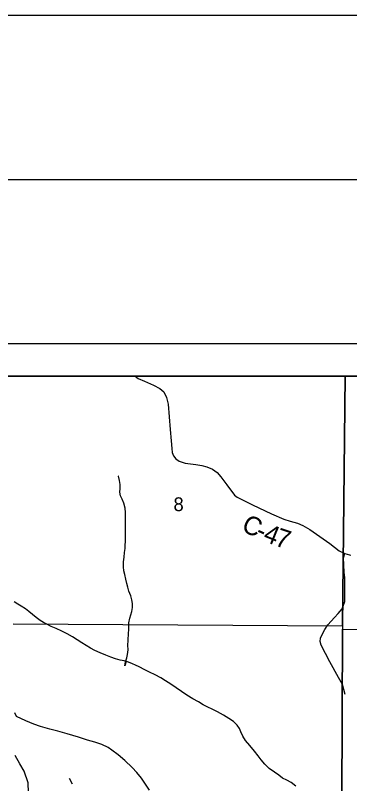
# Model space of a CAD drawing. Extents: x 0 to 34, y 0 to 22.
# Drawn here: x 4.552 to 5.572, y 19.658 to 22 of the extents above; entities that cross this region are included whole.
import ezdxf

# ---------------------------------------------------------------- set-up
doc = ezdxf.new("R2010")
doc.units = 0
for name, color, linetype in [('Default', 7, 'Continuous'), ('GM_X_County_Road', 7, 'Continuous'), ('GM_X_County_Road_Text', 7, 'Continuous'), ('GM_X_Minor_River', 7, 'Continuous'), ('GM_X_Section', 7, 'Continuous'), ('GM_X_Section_Text', 7, 'Continuous'), ('GM_X_State_Route', 7, 'Continuous'), ('GM_X_Township_Road', 7, 'Continuous'), ('SH_Border', 7, 'Continuous'), ('SH_Cut_Line', 7, 'Continuous'), ('SH_Data', 7, 'Continuous')]:
    doc.layers.add(name, color=color, linetype=linetype)

msp = doc.modelspace()

# ---------------------------------------------------------------- linework, layer by layer
at = {"layer": 'Default'}
for p, q in [((7.8225, 20.9), (2.1, 20.9)), ((5.558, 20.9), (4.5485, 20.9)), ((5.5506, 20.1397), (5.558, 20.9)), ((5.558, 20.9), (5.5506, 20.1397)), ((6.4715, 20.9), (5.558, 20.9)), ((4.5449, 20.1449), (5.5506, 20.1397)), ((5.5506, 20.1397), (5.5505, 20.1287)), ((5.5505, 20.1287), (6.4665, 20.1167))]:
    msp.add_line(p, q, dxfattribs=at)
at = {"layer": 'GM_X_County_Road'}
for p, q in [((4.9181, 20.9), (4.9265, 20.8933)), ((4.9265, 20.8933), (4.9456, 20.8848)), ((4.9456, 20.8848), (4.9739, 20.8727)), ((4.9739, 20.8727), (4.9933, 20.8625)), ((4.9933, 20.8625), (5.0055, 20.8526)), ((5.0055, 20.8526), (5.0136, 20.835)), ((5.0136, 20.835), (5.0181, 20.8148)), ((5.0181, 20.8148), (5.0248, 20.7375)), ((5.0248, 20.7375), (5.0275, 20.7027)), ((5.0275, 20.7027), (5.0295, 20.6794)), ((5.0295, 20.6794), (5.0307, 20.6679)), ((5.0307, 20.6679), (5.0341, 20.6576)), ((5.0341, 20.6576), (5.042, 20.6481)), ((5.042, 20.6481), (5.0523, 20.641)), ((5.0523, 20.641), (5.0703, 20.6354)), ((5.0703, 20.6354), (5.1027, 20.6307)), ((5.1027, 20.6307), (5.1207, 20.6279)), ((5.1207, 20.6279), (5.1359, 20.6241)), ((5.1359, 20.6241), (5.1537, 20.6171)), ((5.1537, 20.6171), (5.1678, 20.6066)), ((5.1678, 20.6066), (5.1794, 20.5932)), ((5.1794, 20.5932), (5.1972, 20.5691)), ((5.1972, 20.5691), (5.2206, 20.5378)), ((5.2206, 20.5378), (5.2293, 20.5313)), ((5.2293, 20.5313), (5.2756, 20.5081)), ((5.2756, 20.5081), (5.3338, 20.4804)), ((5.3338, 20.4804), (5.3711, 20.4649)), ((5.3711, 20.4649), (5.3907, 20.4587)), ((5.3907, 20.4587), (5.4131, 20.4521)), ((5.4131, 20.4521), (5.4296, 20.4454)), ((5.4296, 20.4454), (5.4508, 20.4332)), ((5.4508, 20.4332), (5.5114, 20.3899)), ((5.5114, 20.3899), (5.5405, 20.3679)), ((5.5405, 20.3679), (5.5573, 20.3596)), ((5.5573, 20.3596), (5.5717, 20.3552)), ((5.5717, 20.3552), (5.5757, 20.3547))]:
    msp.add_line(p, q, dxfattribs=at)
at = {"layer": 'GM_X_Minor_River'}
for p, q in [((4.8665, 20.595), (4.866, 20.5957)), ((4.8695, 20.5825), (4.8665, 20.595)), ((4.8722, 20.5697), (4.8695, 20.5825)), ((4.8714, 20.5583), (4.8722, 20.5697)), ((4.8706, 20.5465), (4.8714, 20.5583)), ((4.8729, 20.5351), (4.8706, 20.5465)), ((4.8778, 20.525), (4.8729, 20.5351)), ((4.8831, 20.5134), (4.8778, 20.525)), ((4.8866, 20.4979), (4.8831, 20.5134)), ((4.8878, 20.485), (4.8866, 20.4979)), ((4.8878, 20.4732), (4.8878, 20.485)), ((4.8878, 20.4611), (4.8878, 20.4732)), ((4.8885, 20.4512), (4.8878, 20.4611)), ((4.8881, 20.4394), (4.8885, 20.4512)), ((4.8884, 20.428), (4.8881, 20.4394)), ((4.8882, 20.4116), (4.8884, 20.428)), ((4.8875, 20.3854), (4.8883, 20.3968)), ((4.8883, 20.3968), (4.8882, 20.4116)), ((4.8855, 20.3629), (4.887, 20.3751)), ((4.887, 20.3751), (4.8875, 20.3854)), ((4.8837, 20.3484), (4.8855, 20.3629)), ((4.8816, 20.3194), (4.8819, 20.3343)), ((4.8819, 20.3343), (4.8837, 20.3484)), ((4.8827, 20.3073), (4.8816, 20.3194)), ((4.8857, 20.296), (4.8827, 20.3073)), ((4.8892, 20.2816), (4.8857, 20.296)), ((4.8919, 20.2688), (4.8892, 20.2816)), ((4.8949, 20.2575), (4.8919, 20.2688)), ((4.8987, 20.2447), (4.8949, 20.2575)), ((4.9041, 20.2304), (4.8987, 20.2447)), ((4.5601, 20.2052), (4.5488, 20.2124)), ((4.9075, 20.2187), (4.9041, 20.2304)), ((4.9094, 20.2078), (4.9075, 20.2187)), ((4.5698, 20.199), (4.5601, 20.2052)), ((4.5826, 20.1907), (4.5698, 20.199)), ((4.5931, 20.1826), (4.5826, 20.1907)), ((4.9079, 20.1826), (4.9098, 20.1952)), ((4.9098, 20.1952), (4.9094, 20.2078)), ((4.604, 20.1742), (4.5931, 20.1826)), ((4.6157, 20.1647), (4.604, 20.1742)), ((4.6278, 20.156), (4.6157, 20.1647)), ((4.8987, 20.1485), (4.9017, 20.1626)), ((4.9017, 20.1626), (4.9079, 20.1826)), ((4.6375, 20.1498), (4.6278, 20.156)), ((4.6479, 20.144), (4.6375, 20.1498)), ((4.661, 20.1372), (4.6479, 20.144)), ((4.8983, 20.1382), (4.8987, 20.1485)), ((4.6765, 20.1309), (4.661, 20.1372)), ((4.6934, 20.123), (4.6765, 20.1309)), ((4.71, 20.1148), (4.6934, 20.123)), ((4.8958, 20.0948), (4.8974, 20.1169)), ((4.8974, 20.1169), (4.8982, 20.1272)), ((4.8982, 20.1272), (4.8983, 20.1382)), ((4.7263, 20.1054), (4.71, 20.1148)), ((4.741, 20.0968), (4.7263, 20.1054)), ((4.7546, 20.0877), (4.741, 20.0968)), ((4.8955, 20.0807), (4.8958, 20.0948)), ((4.7678, 20.079), (4.7546, 20.0877)), ((4.781, 20.071), (4.7678, 20.079)), ((4.7945, 20.0638), (4.781, 20.071)), ((4.8959, 20.0666), (4.8955, 20.0807)), ((4.8107, 20.0571), (4.7945, 20.0638)), ((4.8284, 20.0501), (4.8107, 20.0571)), ((4.8438, 20.0441), (4.8284, 20.0501)), ((4.8922, 20.0414), (4.8945, 20.0522)), ((4.8945, 20.0522), (4.8959, 20.0666)), ((4.858, 20.0388), (4.8438, 20.0441)), ((4.8715, 20.0351), (4.858, 20.0388)), ((4.8845, 20.0321), (4.8715, 20.0351)), ((4.8968, 20.0283), (4.8845, 20.0321)), ((4.8897, 20.0305), (4.8857, 20.0177)), ((4.8857, 20.0177), (4.8884, 20.0288)), ((4.8884, 20.0288), (4.8922, 20.0414)), ((4.9095, 20.0233), (4.8968, 20.0283)), ((4.9191, 20.0191), (4.9095, 20.0233)), ((4.9295, 20.0141), (4.9191, 20.0191)), ((4.9473, 20.0051), (4.9295, 20.0141)), ((4.9616, 19.998), (4.9473, 20.0051)), ((4.979, 19.9898), (4.9616, 19.998)), ((4.9956, 19.9804), (4.979, 19.9898)), ((5.0103, 19.9721), (4.9956, 19.9804)), ((5.0262, 19.9612), (5.0103, 19.9721)), ((5.0425, 19.9503), (5.0262, 19.9612)), ((5.0589, 19.9394), (5.0425, 19.9503)), ((5.0756, 19.9278), (5.0589, 19.9394)), ((5.0938, 19.917), (5.0756, 19.9278)), ((5.1104, 19.9072), (5.0938, 19.917)), ((5.1255, 19.8986), (5.1104, 19.9072)), ((5.139, 19.8918), (5.1255, 19.8986)), ((5.1529, 19.8854), (5.139, 19.8918)), ((5.1692, 19.8767), (5.1529, 19.8854)), ((5.1874, 19.8667), (5.1692, 19.8767)), ((5.2036, 19.8569), (5.1874, 19.8667)), ((5.2176, 19.8475), (5.2036, 19.8569)), ((5.229, 19.8364), (5.2176, 19.8475)), ((5.2358, 19.8264), (5.229, 19.8364)), ((5.2403, 19.8159), (5.2358, 19.8264)), ((5.246, 19.8027), (5.2403, 19.8159)), ((5.2544, 19.7901), (5.246, 19.8027)), ((5.2674, 19.7741), (5.2544, 19.7901)), ((5.2813, 19.7574), (5.2674, 19.7741)), ((5.2928, 19.7426), (5.2813, 19.7574)), ((5.3023, 19.7304), (5.2928, 19.7426)), ((5.3129, 19.7178), (5.3023, 19.7304)), ((5.3267, 19.7045), (5.3129, 19.7178)), ((5.3426, 19.6936), (5.3267, 19.7045)), ((4.7268, 19.657), (4.7171, 19.6739)), ((5.3558, 19.6837), (5.3426, 19.6936)), ((5.3675, 19.6754), (5.3558, 19.6837)), ((5.3803, 19.6685), (5.3675, 19.6754)), ((5.3934, 19.6617), (5.3803, 19.6685)), ((5.4082, 19.6508), (5.3934, 19.6617))]:
    msp.add_line(p, q, dxfattribs=at)
at = {"layer": 'GM_X_Section'}
for p, q in [((4.5449, 20.1449), (5.5506, 20.1397)), ((5.5506, 20.1397), (5.5505, 20.1287)), ((5.5505, 20.1287), (5.5458, 19.1336)), ((5.5458, 19.1336), (5.5505, 20.1287)), ((5.5505, 20.1287), (6.4665, 20.1167))]:
    msp.add_line(p, q, dxfattribs=at)
at = {"layer": 'GM_X_State_Route'}
for p, q in [((4.5554, 19.8631), (4.5505, 19.8741)), ((4.5837, 19.8496), (4.5554, 19.8631)), ((4.6085, 19.8394), (4.5837, 19.8496)), ((4.6284, 19.8326), (4.6085, 19.8394)), ((4.6574, 19.8248), (4.6284, 19.8326)), ((4.6821, 19.8184), (4.6574, 19.8248)), ((4.7103, 19.8103), (4.6821, 19.8184)), ((4.7447, 19.7999), (4.7103, 19.8103)), ((4.7725, 19.791), (4.7447, 19.7999)), ((4.7943, 19.7846), (4.7725, 19.791)), ((4.816, 19.7774), (4.7943, 19.7846)), ((4.8348, 19.7686), (4.816, 19.7774)), ((4.8467, 19.7601), (4.8348, 19.7686)), ((4.8655, 19.7457), (4.8467, 19.7601)), ((4.8856, 19.7286), (4.8655, 19.7457)), ((4.9084, 19.707), (4.8856, 19.7286)), ((4.9227, 19.6918), (4.9084, 19.707)), ((4.9367, 19.6753), (4.9227, 19.6918)), ((4.9476, 19.66), (4.9367, 19.6753)), ((4.9609, 19.6382), (4.9476, 19.66))]:
    msp.add_line(p, q, dxfattribs=at)
at = {"layer": 'GM_X_Township_Road'}
for p, q in [((5.5537, 20.3469), (5.5573, 20.3596)), ((5.5549, 20.3024), (5.5537, 20.3469)), ((5.5571, 20.2864), (5.5549, 20.3024)), ((5.5569, 20.2395), (5.5571, 20.2864)), ((5.5569, 20.2133), (5.5569, 20.2395)), ((5.5488, 20.191), (5.5569, 20.2133)), ((5.5371, 20.1773), (5.5488, 20.191)), ((5.5054, 20.1423), (5.526, 20.1642)), ((5.526, 20.1642), (5.5371, 20.1773)), ((5.4964, 20.1284), (5.5054, 20.1423)), ((5.4871, 20.1106), (5.4964, 20.1284)), ((5.4819, 20.0918), (5.4835, 20.1013)), ((5.4855, 20.0804), (5.4819, 20.0918)), ((5.4835, 20.1013), (5.4871, 20.1106)), ((5.5118, 20.0291), (5.4855, 20.0804)), ((5.5376, 19.982), (5.5118, 20.0291)), ((5.55, 19.9603), (5.5376, 19.982)), ((5.5582, 19.9296), (5.55, 19.9603)), ((4.5655, 19.7188), (4.5515, 19.7444)), ((4.579, 19.6959), (4.5655, 19.7188)), ((4.5912, 19.6607), (4.579, 19.6959)), ((4.5924, 19.6316), (4.5912, 19.6607))]:
    msp.add_line(p, q, dxfattribs=at)
at = {"layer": 'SH_Border'}
msp.add_lwpolyline([(1.5, 21.5), (33.5, 21.5), (33.5, 0.5), (1.5, 0.5)], close=True, dxfattribs=at)
at = {"layer": 'SH_Cut_Line'}
msp.add_line((7.8225, 20.9), (2.1, 20.9), dxfattribs=at)
msp.add_lwpolyline([(0, 0), (34, 0), (34, 22), (0, 22)], close=True, dxfattribs=at)
at = {"layer": 'SH_Data'}
for p, q in [((2, 21), (9, 21)), ((2.1, 20.9), (8.9, 20.9))]:
    msp.add_line(p, q, dxfattribs=at)

# ---------------------------------------------------------------- texts
at = {"layer": 'GM_X_County_Road_Text'}
for s, rotation, p in [('C', 334.6746, (5.2387, 20.4304)), ('-', 335.7262, (5.2816, 20.4101)), ('4', 337.8731, (5.3048, 20.3997)), ('7', 341.3807, (5.3405, 20.3853))]:
    msp.add_text(s, height=0.0568, rotation=rotation, dxfattribs=at).set_placement(p)
at = {"layer": 'GM_X_Section_Text'}
msp.add_text('8', height=0.0419, rotation=0, dxfattribs=at).set_placement((5.0346, 20.489))

doc.saveas('drawing.dxf')
